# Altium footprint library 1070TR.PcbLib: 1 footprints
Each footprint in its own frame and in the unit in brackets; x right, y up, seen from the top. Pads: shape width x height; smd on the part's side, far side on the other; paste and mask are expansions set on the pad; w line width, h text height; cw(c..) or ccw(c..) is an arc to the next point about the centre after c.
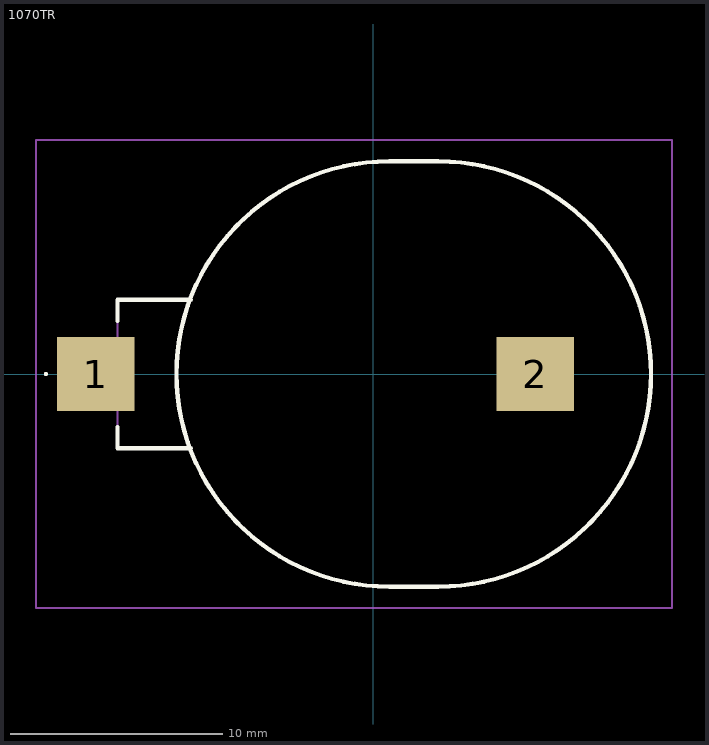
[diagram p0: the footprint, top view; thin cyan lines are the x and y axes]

## 1070TR [mm]
pads (2):
  rect 3.65x3.51 smd: 1(-13.103,0) 2(7.647,0)
Top Overlay:
  lines w0.1: -15.5,0 cw(c-15.45,0) -15.4,0 ; -15.5,0 -15.5,0 ; -15.5,0 ccw(c-15.45,0) -15.4,0 ; -15.4,0 -15.4,0
  lines w0.2: -12.078,-2.5 -12.078,-3.5 -8.613,-3.5 ; -12.078,2.5 -12.078,3.5 -8.613,3.5 ; 0.747,-10.035 3.068,-10.035 ccw(c3.068,0) 3.068,10.035 ; 0.747,-10.035 0.747,-10.035 ; 0.747,-10.035 cw(c0.747,0) 0.747,10.035 1.907,10.035 3.068,10.035 ; 3.068,10.035 3.068,10.035
Mechanical 15:
  lines w0.1: -8.613,-3.5 -12.078,-3.5 -12.078,3.5 -8.613,3.5 ; 0.747,-10.035 3.068,-10.035 ccw(c3.068,0) 3.068,10.035 ; 0.747,-10.035 0.747,-10.035 ; 0.747,-10.035 cw(c0.747,0) 0.747,10.035 1.907,10.035 3.068,10.035 ; 3.068,10.035 3.068,10.035
Mechanical 20:
  lines w0.1: -15.928,-11.035 14.103,-11.035 14.103,11.035 -15.928,11.035 -15.928,-11.035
